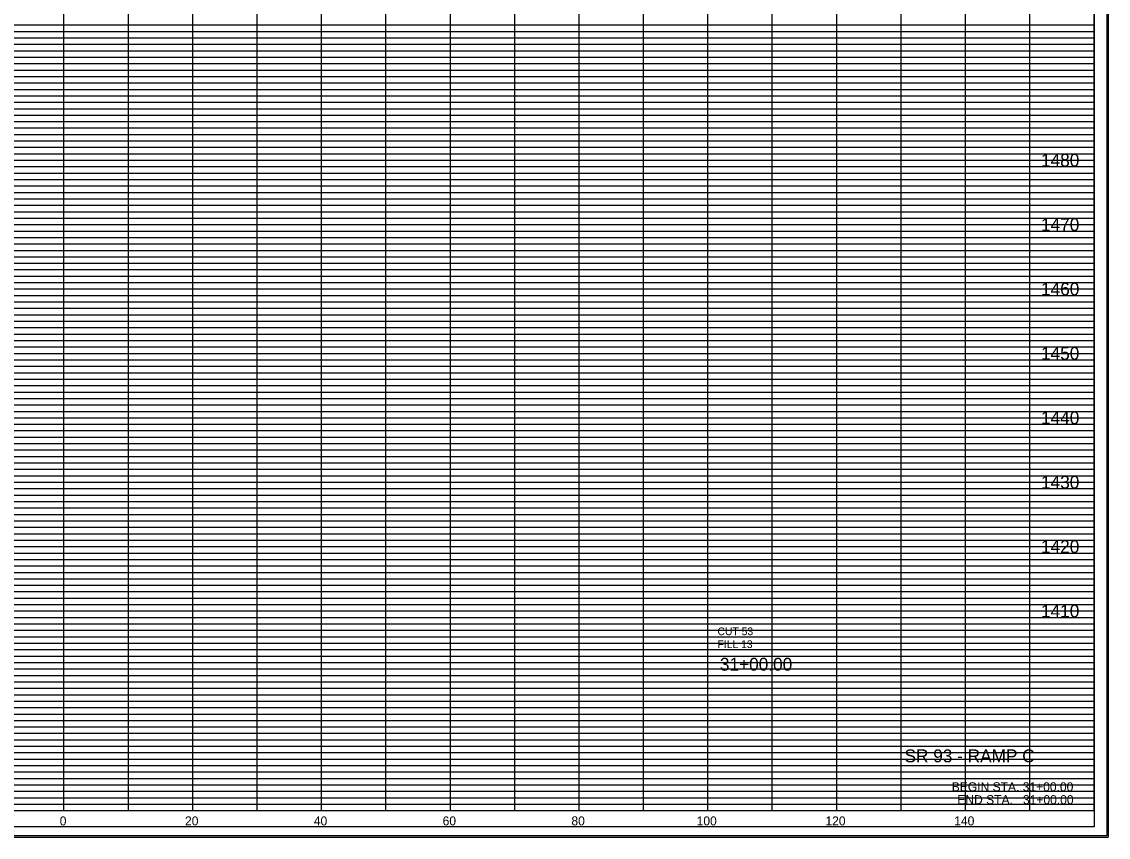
# Model space of a CAD drawing. Extents: x 980 to 2064, y 978 to 2267.
# Drawn here: x 1153.4 to 1322.2, y 1255.9 to 1382.5 of the extents above; entities that cross this region are included whole.
import ezdxf

# ---------------------------------------------------------------- set-up
doc = ezdxf.new("R2010")
doc.units = 0
for name, color, linetype in [('Default', 7, 'Continuous'), ('DESIGN - SHEET - Corner Text', 7, 'Continuous'), ('DESIGN - SHEET - Light Grid', 7, 'Continuous'), ('DESIGN - SHEET - Linework', 7, 'Continuous'), ('DESIGN - SHEET - Plot Shape', 7, 'Continuous'), ('DESIGN - TYPICAL - Text', 7, 'Continuous')]:
    doc.layers.add(name, color=color, linetype=linetype)

msp = doc.modelspace()

# ---------------------------------------------------------------- linework, layer by layer
at = {"layer": 'DESIGN - SHEET - Light Grid'}
for p, q in [((1080, 1382), (1160, 1382)), ((1160, 1382), (1240, 1382)), ((1240, 1382), (1320, 1382)), ((1080, 1381), (1160, 1381)), ((1160, 1381), (1240, 1381)), ((1240, 1381), (1320, 1381)), ((1080, 1379), (1160, 1379)), ((1160, 1379), (1240, 1379)), ((1240, 1379), (1320, 1379)), ((1080, 1378), (1160, 1378)), ((1080, 1377), (1160, 1377)), ((1160, 1378), (1240, 1378)), ((1160, 1377), (1240, 1377)), ((1240, 1378), (1320, 1378)), ((1240, 1377), (1320, 1377)), ((1080, 1376), (1160, 1376)), ((1160, 1376), (1240, 1376)), ((1240, 1376), (1320, 1376)), ((1080, 1375), (1160, 1375)), ((1080, 1374), (1160, 1374)), ((1160, 1375), (1240, 1375)), ((1160, 1374), (1240, 1374)), ((1240, 1375), (1320, 1375)), ((1240, 1374), (1320, 1374)), ((1080, 1373), (1160, 1373)), ((1080, 1372), (1160, 1372)), ((1160, 1373), (1240, 1373)), ((1160, 1372), (1240, 1372)), ((1240, 1373), (1320, 1373)), ((1240, 1372), (1320, 1372)), ((1080, 1371), (1160, 1371)), ((1160, 1371), (1240, 1371)), ((1240, 1371), (1320, 1371)), ((1080, 1369), (1160, 1369)), ((1160, 1369), (1240, 1369)), ((1240, 1369), (1320, 1369)), ((1080, 1368), (1160, 1368)), ((1080, 1367), (1160, 1367)), ((1160, 1368), (1240, 1368)), ((1160, 1367), (1240, 1367)), ((1240, 1368), (1320, 1368)), ((1240, 1367), (1320, 1367)), ((1080, 1366), (1160, 1366)), ((1160, 1366), (1240, 1366)), ((1240, 1366), (1320, 1366)), ((1080, 1365), (1160, 1365)), ((1080, 1364), (1160, 1364)), ((1160, 1365), (1240, 1365)), ((1160, 1364), (1240, 1364)), ((1240, 1365), (1320, 1365)), ((1240, 1364), (1320, 1364)), ((1080, 1363), (1160, 1363)), ((1080, 1362), (1160, 1362)), ((1160, 1363), (1240, 1363)), ((1160, 1362), (1240, 1362)), ((1240, 1363), (1320, 1363)), ((1240, 1362), (1320, 1362)), ((1080, 1361), (1160, 1361)), ((1160, 1361), (1240, 1361)), ((1240, 1361), (1320, 1361)), ((1080, 1359), (1160, 1359)), ((1160, 1359), (1240, 1359)), ((1240, 1359), (1320, 1359)), ((1080, 1358), (1160, 1358)), ((1080, 1357), (1160, 1357)), ((1160, 1358), (1240, 1358)), ((1160, 1357), (1240, 1357)), ((1240, 1358), (1320, 1358)), ((1240, 1357), (1320, 1357)), ((1080, 1356), (1160, 1356)), ((1080, 1355), (1160, 1355)), ((1160, 1356), (1240, 1356)), ((1160, 1355), (1240, 1355)), ((1240, 1356), (1320, 1356)), ((1240, 1355), (1320, 1355)), ((1080, 1354), (1160, 1354)), ((1160, 1354), (1240, 1354)), ((1240, 1354), (1320, 1354)), ((1080, 1353), (1160, 1353)), ((1080, 1352), (1160, 1352)), ((1160, 1353), (1240, 1353)), ((1160, 1352), (1240, 1352)), ((1240, 1353), (1320, 1353)), ((1240, 1352), (1320, 1352)), ((1080, 1351), (1160, 1351)), ((1160, 1351), (1240, 1351)), ((1240, 1351), (1320, 1351)), ((1080, 1349), (1160, 1349)), ((1160, 1349), (1240, 1349)), ((1240, 1349), (1320, 1349)), ((1080, 1348), (1160, 1348)), ((1080, 1347), (1160, 1347)), ((1160, 1348), (1240, 1348)), ((1160, 1347), (1240, 1347)), ((1240, 1348), (1320, 1348)), ((1240, 1347), (1320, 1347)), ((1080, 1346), (1160, 1346)), ((1080, 1345), (1160, 1345)), ((1160, 1346), (1240, 1346)), ((1160, 1345), (1240, 1345)), ((1240, 1346), (1320, 1346)), ((1240, 1345), (1320, 1345)), ((1080, 1344), (1160, 1344)), ((1160, 1344), (1240, 1344)), ((1240, 1344), (1320, 1344)), ((1080, 1343), (1160, 1343)), ((1080, 1342), (1160, 1342)), ((1160, 1343), (1240, 1343)), ((1160, 1342), (1240, 1342)), ((1240, 1343), (1320, 1343)), ((1240, 1342), (1320, 1342)), ((1080, 1341), (1160, 1341)), ((1160, 1341), (1240, 1341)), ((1240, 1341), (1320, 1341)), ((1080, 1339), (1160, 1339)), ((1160, 1339), (1240, 1339)), ((1240, 1339), (1320, 1339)), ((1080, 1338), (1160, 1338)), ((1080, 1337), (1160, 1337)), ((1160, 1338), (1240, 1338)), ((1160, 1337), (1240, 1337)), ((1240, 1338), (1320, 1338)), ((1240, 1337), (1320, 1337)), ((1080, 1336), (1160, 1336)), ((1080, 1335), (1160, 1335)), ((1160, 1336), (1240, 1336)), ((1160, 1335), (1240, 1335)), ((1240, 1336), (1320, 1336)), ((1240, 1335), (1320, 1335)), ((1080, 1334), (1160, 1334)), ((1080, 1333), (1160, 1333)), ((1160, 1334), (1240, 1334)), ((1160, 1333), (1240, 1333)), ((1240, 1334), (1320, 1334)), ((1240, 1333), (1320, 1333)), ((1080, 1332), (1160, 1332)), ((1160, 1332), (1240, 1332)), ((1240, 1332), (1320, 1332)), ((1080, 1331), (1160, 1331)), ((1160, 1331), (1240, 1331)), ((1240, 1331), (1320, 1331)), ((1080, 1329), (1160, 1329)), ((1080, 1328), (1160, 1328)), ((1160, 1329), (1240, 1329)), ((1160, 1328), (1240, 1328)), ((1240, 1329), (1320, 1329)), ((1240, 1328), (1320, 1328)), ((1080, 1327), (1160, 1327)), ((1160, 1327), (1240, 1327)), ((1240, 1327), (1320, 1327)), ((1080, 1326), (1160, 1326)), ((1080, 1325), (1160, 1325)), ((1160, 1326), (1240, 1326)), ((1160, 1325), (1240, 1325)), ((1240, 1326), (1320, 1326)), ((1240, 1325), (1320, 1325)), ((1080, 1324), (1160, 1324)), ((1080, 1323), (1160, 1323)), ((1160, 1324), (1240, 1324)), ((1160, 1323), (1240, 1323)), ((1240, 1324), (1320, 1324)), ((1240, 1323), (1320, 1323)), ((1080, 1322), (1160, 1322)), ((1160, 1322), (1240, 1322)), ((1240, 1322), (1320, 1322)), ((1080, 1321), (1160, 1321)), ((1160, 1321), (1240, 1321)), ((1240, 1321), (1320, 1321)), ((1080, 1319), (1160, 1319)), ((1080, 1318), (1160, 1318)), ((1160, 1319), (1240, 1319)), ((1160, 1318), (1240, 1318)), ((1240, 1319), (1320, 1319)), ((1240, 1318), (1320, 1318)), ((1080, 1317), (1160, 1317)), ((1160, 1317), (1240, 1317)), ((1240, 1317), (1320, 1317)), ((1080, 1316), (1160, 1316)), ((1080, 1315), (1160, 1315)), ((1160, 1316), (1240, 1316)), ((1160, 1315), (1240, 1315)), ((1240, 1316), (1320, 1316)), ((1240, 1315), (1320, 1315)), ((1080, 1314), (1160, 1314)), ((1080, 1313), (1160, 1313)), ((1160, 1314), (1240, 1314)), ((1160, 1313), (1240, 1313)), ((1240, 1314), (1320, 1314)), ((1240, 1313), (1320, 1313)), ((1080, 1312), (1160, 1312)), ((1160, 1312), (1240, 1312)), ((1240, 1312), (1320, 1312)), ((1080, 1311), (1160, 1311)), ((1160, 1311), (1240, 1311)), ((1240, 1311), (1320, 1311)), ((1080, 1309), (1160, 1309)), ((1080, 1308), (1160, 1308)), ((1160, 1309), (1240, 1309)), ((1160, 1308), (1240, 1308)), ((1240, 1309), (1320, 1309)), ((1240, 1308), (1320, 1308)), ((1080, 1307), (1160, 1307)), ((1080, 1306), (1160, 1306)), ((1160, 1307), (1240, 1307)), ((1160, 1306), (1240, 1306)), ((1240, 1307), (1320, 1307)), ((1240, 1306), (1320, 1306)), ((1080, 1305), (1160, 1305)), ((1160, 1305), (1240, 1305)), ((1240, 1305), (1320, 1305)), ((1080, 1304), (1160, 1304)), ((1080, 1303), (1160, 1303)), ((1160, 1304), (1240, 1304)), ((1160, 1303), (1240, 1303)), ((1240, 1304), (1320, 1304)), ((1240, 1303), (1320, 1303)), ((1080, 1302), (1160, 1302)), ((1080, 1301), (1160, 1301)), ((1160, 1302), (1240, 1302)), ((1160, 1301), (1240, 1301)), ((1240, 1302), (1320, 1302)), ((1240, 1301), (1320, 1301)), ((1080, 1299), (1160, 1299)), ((1080, 1298), (1160, 1298)), ((1160, 1299), (1240, 1299)), ((1160, 1298), (1240, 1298)), ((1240, 1299), (1320, 1299)), ((1240, 1298), (1320, 1298)), ((1080, 1297), (1160, 1297)), ((1080, 1296), (1160, 1296)), ((1160, 1297), (1240, 1297)), ((1160, 1296), (1240, 1296)), ((1240, 1297), (1320, 1297)), ((1240, 1296), (1320, 1296)), ((1080, 1295), (1160, 1295)), ((1160, 1295), (1240, 1295)), ((1240, 1295), (1320, 1295)), ((1080, 1294), (1160, 1294)), ((1080, 1293), (1160, 1293)), ((1160, 1294), (1240, 1294)), ((1160, 1293), (1240, 1293)), ((1240, 1294), (1320, 1294)), ((1240, 1293), (1320, 1293)), ((1080, 1292), (1160, 1292)), ((1080, 1291), (1160, 1291)), ((1160, 1292), (1240, 1292)), ((1160, 1291), (1240, 1291)), ((1240, 1292), (1320, 1292)), ((1240, 1291), (1320, 1291)), ((1080, 1289), (1160, 1289)), ((1080, 1288), (1160, 1288)), ((1160, 1289), (1240, 1289)), ((1160, 1288), (1240, 1288)), ((1240, 1289), (1320, 1289)), ((1240, 1288), (1320, 1288)), ((1080, 1287), (1160, 1287)), ((1080, 1286), (1160, 1286)), ((1160, 1287), (1240, 1287)), ((1160, 1286), (1240, 1286)), ((1240, 1287), (1320, 1287)), ((1240, 1286), (1320, 1286)), ((1080, 1285), (1160, 1285)), ((1160, 1285), (1240, 1285)), ((1240, 1285), (1320, 1285)), ((1080, 1284), (1160, 1284)), ((1080, 1283), (1160, 1283)), ((1160, 1284), (1240, 1284)), ((1160, 1283), (1240, 1283)), ((1240, 1284), (1320, 1284)), ((1240, 1283), (1320, 1283)), ((1080, 1282), (1160, 1282)), ((1080, 1281), (1160, 1281)), ((1160, 1282), (1240, 1282)), ((1160, 1281), (1240, 1281)), ((1240, 1282), (1320, 1282)), ((1240, 1281), (1320, 1281)), ((1080, 1279), (1160, 1279)), ((1160, 1279), (1240, 1279)), ((1240, 1279), (1320, 1279)), ((1080, 1278), (1160, 1278)), ((1160, 1278), (1240, 1278)), ((1240, 1278), (1320, 1278)), ((1080, 1277), (1160, 1277)), ((1080, 1276), (1160, 1276)), ((1160, 1277), (1240, 1277)), ((1160, 1276), (1240, 1276)), ((1240, 1277), (1320, 1277)), ((1240, 1276), (1320, 1276)), ((1080, 1275), (1160, 1275)), ((1080, 1274), (1160, 1274)), ((1160, 1275), (1240, 1275)), ((1160, 1274), (1240, 1274)), ((1240, 1275), (1320, 1275)), ((1240, 1274), (1320, 1274)), ((1080, 1273), (1160, 1273)), ((1160, 1273), (1240, 1273)), ((1240, 1273), (1320, 1273)), ((1080, 1272), (1160, 1272)), ((1080, 1271), (1160, 1271)), ((1160, 1272), (1240, 1272)), ((1160, 1271), (1240, 1271)), ((1240, 1272), (1320, 1272)), ((1240, 1271), (1320, 1271)), ((1080, 1269), (1160, 1269)), ((1160, 1269), (1240, 1269)), ((1240, 1269), (1320, 1269)), ((1080, 1268), (1160, 1268)), ((1160, 1268), (1240, 1268)), ((1240, 1268), (1320, 1268)), ((1080, 1267), (1160, 1267)), ((1080, 1266), (1160, 1266)), ((1160, 1267), (1240, 1267)), ((1160, 1266), (1240, 1266)), ((1240, 1267), (1320, 1267)), ((1240, 1266), (1320, 1266)), ((1080, 1265), (1160, 1265)), ((1080, 1264), (1160, 1264)), ((1160, 1265), (1240, 1265)), ((1160, 1264), (1240, 1264)), ((1240, 1265), (1320, 1265)), ((1240, 1264), (1320, 1264)), ((1080, 1263), (1160, 1263)), ((1160, 1263), (1240, 1263)), ((1240, 1263), (1320, 1263)), ((1080, 1262), (1160, 1262)), ((1080, 1261), (1160, 1261)), ((1160, 1262), (1240, 1262)), ((1160, 1261), (1240, 1261)), ((1240, 1262), (1320, 1262)), ((1240, 1261), (1320, 1261))]:
    msp.add_line(p, q, dxfattribs=at)
at = {"layer": 'DESIGN - SHEET - Linework'}
for p, q in [((1322.17, 1474.14), (1322.17, 1255.86)), ((1160, 1260), (1160, 1470)), ((1170, 1260), (1170, 1470)), ((1180, 1260), (1180, 1470)), ((1190, 1260), (1190, 1470)), ((1200, 1260), (1200, 1470)), ((1210, 1260), (1210, 1470)), ((1220, 1260), (1220, 1470)), ((1230, 1260), (1230, 1470)), ((1240, 1260), (1240, 1470)), ((1250, 1260), (1250, 1470)), ((1260, 1260), (1260, 1470)), ((1270, 1260), (1270, 1470)), ((1280, 1260), (1280, 1460)), ((1290, 1260), (1290, 1460)), ((1300, 1260), (1300, 1460)), ((1310, 1260), (1310, 1460)), ((1000, 1380), (1320, 1380)), ((1000, 1370), (1320, 1370)), ((1000, 1360), (1320, 1360)), ((1000, 1350), (1320, 1350)), ((1000, 1340), (1320, 1340)), ((1000, 1330), (1320, 1330)), ((1000, 1320), (1320, 1320)), ((1000, 1310), (1320, 1310)), ((1000, 1300), (1320, 1300)), ((1000, 1290), (1320, 1290)), ((1000, 1280), (1320, 1280)), ((1000, 1270), (1320, 1270)), ((981.77, 1255.86), (1322.17, 1255.86))]:
    msp.add_line(p, q, dxfattribs=at)
msp.add_lwpolyline([(1000, 1470), (1000, 1260), (1320, 1260), (1320, 1470), (1000, 1470)], dxfattribs=at)
at = {"layer": 'DESIGN - SHEET - Plot Shape'}
for points in [[(981.97, 1473.94), (1321.97, 1473.94), (1321.97, 1256.06), (981.97, 1256.06)], [(991.5, 1470), (1320, 1470), (1320, 1257.5), (991.5, 1257.5)]]:
    msp.add_lwpolyline(points, close=True, dxfattribs=at)

# ---------------------------------------------------------------- texts
at = {"layer": 'Default'}
for s, height, p in [('     1480     ', 2, (1308.01, 1360)), ('     1470     ', 2, (1308.01, 1350)), ('     1460     ', 2, (1308.01, 1340)), ('     1450     ', 2, (1308.01, 1330)), ('     1440     ', 2, (1308.01, 1320)), ('     1430     ', 2, (1308.01, 1310)), ('     1420     ', 2, (1308.01, 1300)), ('     1410     ', 2, (1308.01, 1290)), ('     31+00.00     ', 2, (1258.15, 1281.73)), ('     0     ', 1.4, (1156.74, 1257.7)), ('     0     ', 1.4, (1156.74, 1257.7)), ('     20     ', 1.4, (1176.2, 1257.7)), ('     40     ', 1.4, (1196.2, 1257.7)), ('     60     ', 1.4, (1216.2, 1257.7)), ('     80     ', 1.4, (1236.2, 1257.7)), ('     100     ', 1.4, (1255.65, 1257.7)), ('     120     ', 1.4, (1275.65, 1257.7)), ('     140     ', 1.4, (1295.65, 1257.7))]:
    msp.add_text(s, height=height, dxfattribs=at).set_placement(p)
at = {"layer": 'DESIGN - SHEET - Corner Text'}
for s, height, p in [('SR 93 - RAMP C', 2, (1290.53, 1267.5)), ('BEGIN STA. 31+00.00', 1.4, (1297.86, 1263)), ('END STA.   31+00.00', 1.4, (1298.73, 1261))]:
    msp.add_text(s, height=height, dxfattribs=at).set_placement(p)
at = {"layer": 'DESIGN - TYPICAL - Text'}
for s, p in [('CUT 53', (1261.49, 1287.24)), ('FILL 13', (1261.49, 1285.24))]:
    msp.add_text(s, height=1.2, dxfattribs=at).set_placement(p)

doc.saveas('drawing.dxf')
